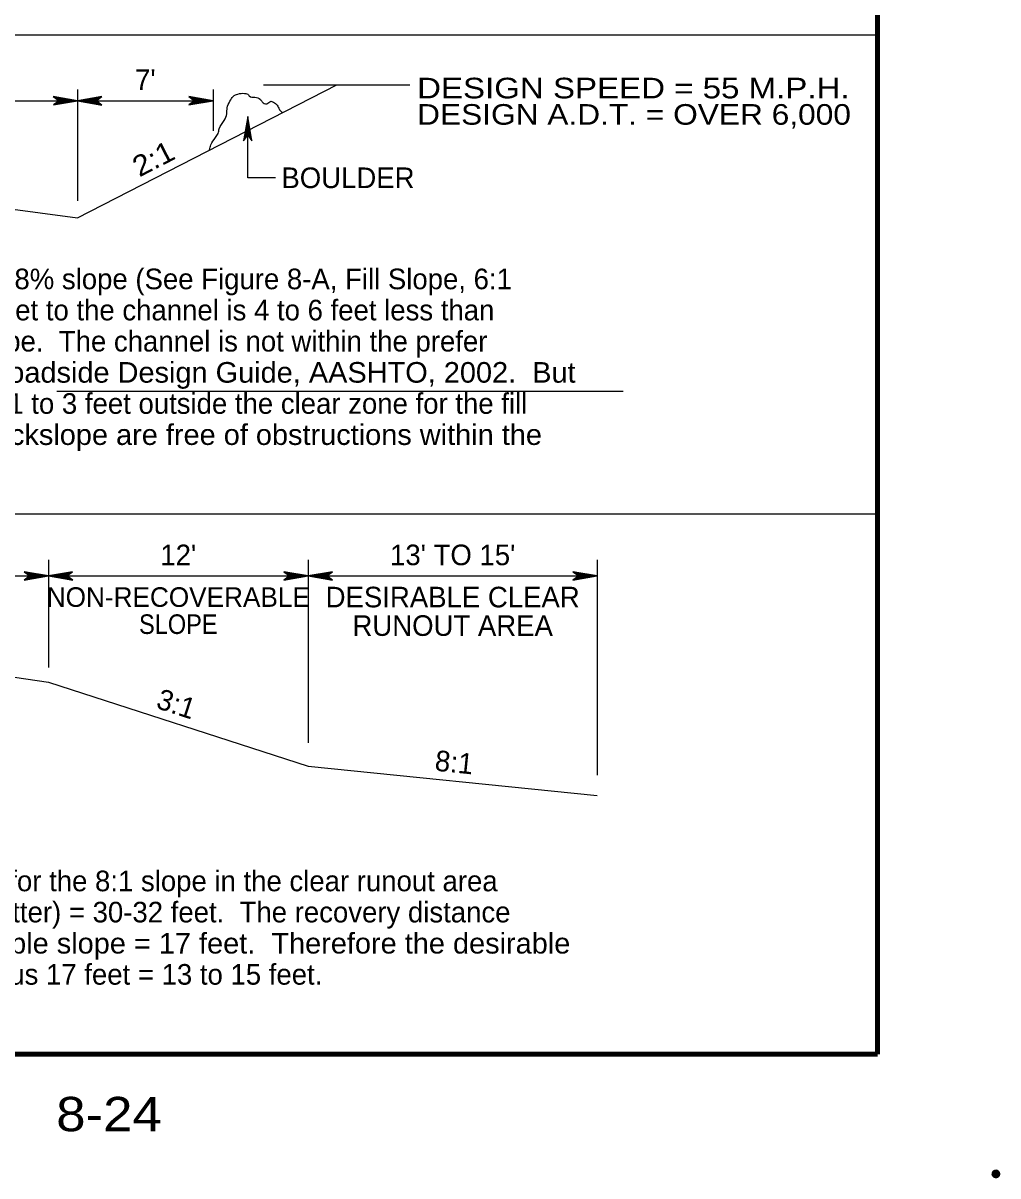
# Model space of a CAD drawing. Extents: x -15.691 to -15.016, y -14.8 to -13.916.
# Drawn here: x -15.3861 to -15.016, y -14.8 to -14.3626 of the extents above; entities that cross this region are included whole.
import ezdxf
from ezdxf.enums import TextEntityAlignment as Align

# ---------------------------------------------------------------- set-up
doc = ezdxf.new("R2010")
doc.units = 0
doc.header["$LTSCALE"] = 0.0031
doc.header["$PDMODE"] = 32
doc.header["$PDSIZE"] = 0.00155
for name, color, linetype, lineweight in [('1', 7, 'Continuous', 90), ('24', 7, 'Continuous', 25), ('5', 7, 'Continuous', 25)]:
    doc.layers.add(name, color=color, linetype=linetype, lineweight=lineweight)

msp = doc.modelspace()

# ---------------------------------------------------------------- linework, layer by layer
at = {"layer": '1'}
for p, q in [((-15.061808, -13.962108), (-15.061808, -14.753775)), ((-15.061808, -13.962108), (-15.061808, -14.753775)), ((-15.061808, -14.753775), (-15.645142, -14.753775))]:
    msp.add_line(p, q, dxfattribs=at)
msp.add_point((-15.016808, -14.799192), dxfattribs=at)
at = {"layer": '24'}
for p, q in [((-15.365383, -14.387742), (-15.365383, -14.429967)), ((-15.313992, -14.387742), (-15.313992, -14.403408)), ((-15.376492, -14.5662), (-15.376492, -14.607058)), ((-15.277883, -14.5662), (-15.277883, -14.635667)), ((-15.168158, -14.5662), (-15.168158, -14.647925))]:
    msp.add_line(p, q, dxfattribs=at)
for points in [[(-15.365383, -14.392042), (-15.374625, -14.390408), (-15.372417, -14.392042), (-15.374575, -14.39365), (-15.365383, -14.392042), (-15.365992, -14.392058), (-15.374358, -14.390525), (-15.372242, -14.392058), (-15.3742, -14.393517), (-15.366325, -14.392083), (-15.366633, -14.392042), (-15.3738, -14.390767), (-15.372192, -14.392058), (-15.37385, -14.393308), (-15.366775, -14.392042), (-15.367083, -14.392083), (-15.37335, -14.39095), (-15.372125, -14.392042), (-15.373375, -14.393167), (-15.367975, -14.392083), (-15.368492, -14.392083), (-15.372883, -14.391183), (-15.372025, -14.392008), (-15.37295, -14.392933), (-15.368592, -14.392042), (-15.369083, -14.392008), (-15.372383, -14.391442), (-15.37175, -14.392083), (-15.372433, -14.392717), (-15.369533, -14.392042), (-15.37, -14.391992), (-15.371983, -14.391617), (-15.371658, -14.392058), (-15.372192, -14.39255), (-15.370242, -14.392033), (-15.371533, -14.391733), (-15.37135, -14.392083), (-15.371917, -14.392442), (-15.370567, -14.392083), (-15.371417, -14.391875), (-15.371058, -14.39215), (-15.371467, -14.392317), (-15.371058, -14.392058), (-15.371275, -14.392008)], [(-15.365383, -14.392042), (-15.356142, -14.393675), (-15.35835, -14.392042), (-15.356192, -14.390433), (-15.365383, -14.392042), (-15.364767, -14.392025), (-15.3564, -14.39355), (-15.358525, -14.392017), (-15.356558, -14.390558), (-15.364433, -14.391992), (-15.364125, -14.392042), (-15.356958, -14.393308), (-15.358567, -14.392017), (-15.356917, -14.390767), (-15.363992, -14.392042), (-15.363683, -14.391992), (-15.357417, -14.393125), (-15.358633, -14.392042), (-15.357392, -14.390908), (-15.362792, -14.391992), (-15.362267, -14.391992), (-15.357883, -14.392892), (-15.358733, -14.392067), (-15.357817, -14.391142), (-15.362175, -14.392042), (-15.361683, -14.392067), (-15.358383, -14.392633), (-15.359017, -14.391992), (-15.358325, -14.391358), (-15.361225, -14.392042), (-15.360758, -14.392083), (-15.358783, -14.392467), (-15.359108, -14.392017), (-15.358567, -14.391525), (-15.360517, -14.392042), (-15.359225, -14.392342), (-15.359417, -14.391992), (-15.35885, -14.391642), (-15.360192, -14.391992), (-15.35935, -14.3922), (-15.3597, -14.391925), (-15.359292, -14.391758), (-15.3597, -14.392017), (-15.359492, -14.392067)], [(-15.313992, -14.392042), (-15.323233, -14.390408), (-15.321025, -14.392042), (-15.323183, -14.39365), (-15.313992, -14.392042), (-15.314608, -14.392058), (-15.322975, -14.390525), (-15.32085, -14.392058), (-15.322808, -14.393517), (-15.314942, -14.392083), (-15.315242, -14.392042), (-15.322417, -14.390767), (-15.320808, -14.392058), (-15.322458, -14.393308), (-15.315383, -14.392042), (-15.315692, -14.392083), (-15.321958, -14.39095), (-15.320742, -14.392042), (-15.321983, -14.393167), (-15.316583, -14.392083), (-15.317108, -14.392083), (-15.321492, -14.391183), (-15.320642, -14.392008), (-15.321558, -14.392933), (-15.3172, -14.392042), (-15.317692, -14.392008), (-15.320992, -14.391442), (-15.320358, -14.392083), (-15.321042, -14.392717), (-15.31815, -14.392042), (-15.318608, -14.391992), (-15.320592, -14.391617), (-15.320267, -14.392058), (-15.320808, -14.39255), (-15.31885, -14.392033), (-15.320142, -14.391733), (-15.319958, -14.392083), (-15.320525, -14.392442), (-15.319175, -14.392083), (-15.320025, -14.391875), (-15.319675, -14.39215), (-15.320075, -14.392317), (-15.319675, -14.392058), (-15.319883, -14.392008)], [(-15.448717, -14.392042), (-15.365383, -14.392042), (-15.313992, -14.392042)], [(-15.300817, -14.398025), (-15.30245, -14.407267), (-15.300817, -14.405058), (-15.299208, -14.407217), (-15.300817, -14.398025), (-15.3008, -14.398642), (-15.302325, -14.407008), (-15.300792, -14.404883), (-15.299333, -14.406842), (-15.300767, -14.398967), (-15.300817, -14.399275), (-15.302092, -14.40645), (-15.3008, -14.404842), (-15.299542, -14.406492), (-15.300817, -14.399417), (-15.300767, -14.399725), (-15.3019, -14.405992), (-15.300817, -14.404775), (-15.299692, -14.406017), (-15.300767, -14.400617), (-15.300767, -14.401142), (-15.301667, -14.405525), (-15.300842, -14.404675), (-15.299925, -14.405592), (-15.300817, -14.401233), (-15.300842, -14.401725), (-15.301408, -14.405025), (-15.300767, -14.404392), (-15.300133, -14.405075), (-15.300817, -14.402183), (-15.300858, -14.402642), (-15.301242, -14.404625), (-15.300792, -14.4043), (-15.3003, -14.404842), (-15.300817, -14.402883), (-15.301125, -14.404175), (-15.300767, -14.403992), (-15.300417, -14.404558), (-15.300767, -14.403208), (-15.300983, -14.404058), (-15.3007, -14.4037), (-15.300533, -14.404108), (-15.300792, -14.403708), (-15.300842, -14.403917)], [(-15.29025, -14.421267), (-15.300817, -14.421267), (-15.300817, -14.398025)], [(-15.518158, -14.572342), (-15.433433, -14.572342), (-15.376492, -14.572342), (-15.277883, -14.572342), (-15.168158, -14.572342)], [(-15.376492, -14.572342), (-15.385733, -14.570708), (-15.383525, -14.572342), (-15.385683, -14.573942), (-15.376492, -14.572342), (-15.377108, -14.572358), (-15.385475, -14.570825), (-15.38335, -14.572358), (-15.385308, -14.573817), (-15.377433, -14.572383), (-15.377742, -14.572342), (-15.384917, -14.571067), (-15.383308, -14.572358), (-15.384958, -14.573608), (-15.377883, -14.572333), (-15.378192, -14.572383), (-15.384458, -14.57125), (-15.383242, -14.572333), (-15.384483, -14.573467), (-15.379083, -14.572383), (-15.379608, -14.572383), (-15.383992, -14.571483), (-15.383142, -14.572308), (-15.384058, -14.573233), (-15.3797, -14.572342), (-15.380192, -14.572308), (-15.383492, -14.571742), (-15.382858, -14.572383), (-15.383542, -14.573017), (-15.38065, -14.572342), (-15.381108, -14.572292), (-15.383092, -14.571908), (-15.382767, -14.572358), (-15.383308, -14.57285), (-15.38135, -14.572333), (-15.382642, -14.572033), (-15.382458, -14.572383), (-15.383025, -14.572742), (-15.381675, -14.572383), (-15.382525, -14.572175), (-15.382167, -14.57245), (-15.382575, -14.572617), (-15.382175, -14.572358), (-15.382383, -14.572308)], [(-15.376492, -14.572342), (-15.36725, -14.573975), (-15.369458, -14.572342), (-15.3673, -14.570733), (-15.376492, -14.572342), (-15.375875, -14.572317), (-15.367508, -14.57385), (-15.369633, -14.572317), (-15.367675, -14.570858), (-15.37555, -14.572292), (-15.375242, -14.572342), (-15.368075, -14.573608), (-15.369683, -14.572317), (-15.368025, -14.571067), (-15.3751, -14.572342), (-15.374792, -14.572292), (-15.368525, -14.573425), (-15.369742, -14.572342), (-15.3685, -14.571208), (-15.3739, -14.572292), (-15.373375, -14.572292), (-15.368992, -14.573192), (-15.369842, -14.572367), (-15.368925, -14.571442), (-15.373283, -14.572342), (-15.372792, -14.572367), (-15.369492, -14.572933), (-15.370125, -14.572292), (-15.369442, -14.571658), (-15.372342, -14.572342), (-15.371875, -14.572383), (-15.369892, -14.572767), (-15.370217, -14.572317), (-15.369675, -14.571825), (-15.371633, -14.572342), (-15.370342, -14.572642), (-15.370525, -14.572292), (-15.369958, -14.571942), (-15.371308, -14.572292), (-15.370458, -14.5725), (-15.370817, -14.572225), (-15.370408, -14.572058), (-15.370808, -14.572317), (-15.3706, -14.572367)], [(-15.277883, -14.572342), (-15.287125, -14.570708), (-15.284917, -14.572342), (-15.287075, -14.573942), (-15.277883, -14.572342), (-15.278492, -14.572358), (-15.286867, -14.570825), (-15.284742, -14.572358), (-15.2867, -14.573817), (-15.278825, -14.572383), (-15.279133, -14.572342), (-15.2863, -14.571067), (-15.284692, -14.572358), (-15.28635, -14.573608), (-15.279275, -14.572333), (-15.279583, -14.572383), (-15.28585, -14.57125), (-15.284625, -14.572333), (-15.285875, -14.573467), (-15.280475, -14.572383), (-15.280992, -14.572383), (-15.285383, -14.571483), (-15.284533, -14.572308), (-15.28545, -14.573233), (-15.281092, -14.572342), (-15.281583, -14.572308), (-15.284883, -14.571742), (-15.28425, -14.572383), (-15.284933, -14.573017), (-15.282033, -14.572342), (-15.2825, -14.572292), (-15.284483, -14.571908), (-15.284158, -14.572358), (-15.284692, -14.57285), (-15.282742, -14.572333), (-15.284033, -14.572033), (-15.28385, -14.572383), (-15.284417, -14.572742), (-15.283067, -14.572383), (-15.283917, -14.572175), (-15.283558, -14.57245), (-15.283967, -14.572617), (-15.283558, -14.572358), (-15.283775, -14.572308)], [(-15.277883, -14.572342), (-15.268642, -14.573975), (-15.27085, -14.572342), (-15.268692, -14.570733), (-15.277883, -14.572342), (-15.277267, -14.572317), (-15.2689, -14.57385), (-15.271025, -14.572317), (-15.269067, -14.570858), (-15.276933, -14.572292), (-15.276625, -14.572342), (-15.269458, -14.573608), (-15.271067, -14.572317), (-15.269417, -14.571067), (-15.276492, -14.572342), (-15.276183, -14.572292), (-15.269917, -14.573425), (-15.271133, -14.572342), (-15.269892, -14.571208), (-15.275292, -14.572292), (-15.274767, -14.572292), (-15.270383, -14.573192), (-15.271233, -14.572367), (-15.270317, -14.571442), (-15.274675, -14.572342), (-15.274183, -14.572367), (-15.270883, -14.572933), (-15.271517, -14.572292), (-15.270833, -14.571658), (-15.273725, -14.572342), (-15.273258, -14.572383), (-15.271283, -14.572767), (-15.271608, -14.572317), (-15.271067, -14.571825), (-15.273025, -14.572342), (-15.271733, -14.572642), (-15.271917, -14.572292), (-15.27135, -14.571942), (-15.2727, -14.572292), (-15.27185, -14.5725), (-15.2722, -14.572225), (-15.2718, -14.572058), (-15.2722, -14.572317), (-15.271992, -14.572367)], [(-15.168158, -14.572342), (-15.1774, -14.570708), (-15.175192, -14.572342), (-15.17735, -14.573942), (-15.168158, -14.572342), (-15.168775, -14.572358), (-15.177142, -14.570825), (-15.175017, -14.572358), (-15.176975, -14.573817), (-15.169108, -14.572383), (-15.169408, -14.572342), (-15.176583, -14.571067), (-15.174975, -14.572358), (-15.176625, -14.573608), (-15.16955, -14.572333), (-15.169858, -14.572383), (-15.176125, -14.57125), (-15.174908, -14.572333), (-15.17615, -14.573467), (-15.17075, -14.572383), (-15.171275, -14.572383), (-15.175658, -14.571483), (-15.174808, -14.572308), (-15.175725, -14.573233), (-15.171367, -14.572342), (-15.171858, -14.572308), (-15.175158, -14.571742), (-15.174525, -14.572383), (-15.175208, -14.573017), (-15.172317, -14.572342), (-15.172775, -14.572292), (-15.174758, -14.571908), (-15.174433, -14.572358), (-15.174975, -14.57285), (-15.173017, -14.572333), (-15.174308, -14.572033), (-15.174125, -14.572383), (-15.174692, -14.572742), (-15.173342, -14.572383), (-15.174192, -14.572175), (-15.173842, -14.57245), (-15.174242, -14.572617), (-15.173842, -14.572358), (-15.17405, -14.572308)]]:
    msp.add_lwpolyline(points, dxfattribs=at)
at = {"layer": '5'}
for p, q in [((-15.645142, -14.367008), (-15.061808, -14.367008)), ((-15.294825, -14.385983), (-15.267042, -14.385983)), ((-15.373233, -14.5022), (-15.15825, -14.5022)), ((-15.645142, -14.5487), (-15.061808, -14.5487))]:
    msp.add_line(p, q, dxfattribs=at)
for points in [[(-15.518158, -14.419817), (-15.448717, -14.425375), (-15.365383, -14.436483), (-15.267042, -14.385983), (-15.239267, -14.385983)], [(-15.518158, -14.600117), (-15.433433, -14.604283), (-15.376492, -14.612617), (-15.277883, -14.644558), (-15.168158, -14.655675)]]:
    msp.add_lwpolyline(points, dxfattribs=at)
msp.add_spline([(-15.315383, -14.410692), (-15.314817, -14.408733), (-15.3131, -14.406042), (-15.312042, -14.404408), (-15.311633, -14.4027), (-15.309758, -14.399517), (-15.308783, -14.396992), (-15.308617, -14.394708), (-15.307558, -14.392183), (-15.306333, -14.390383), (-15.304542, -14.389492), (-15.302008, -14.389242), (-15.300542, -14.389817), (-15.300217, -14.390225), (-15.298183, -14.390717), (-15.295975, -14.391608), (-15.295325, -14.392425), (-15.293617, -14.393158), (-15.292067, -14.392258), (-15.290675, -14.392833), (-15.289375, -14.394142), (-15.288717, -14.395442), (-15.287742, -14.396425)], degree=3, dxfattribs=at)

# ---------------------------------------------------------------- texts
at = {"layer": '1'}
for s, height, p in [("7'", 0.007817, (-15.339683, -14.38795)), ('BOULDER', 0.007817, (-15.262775, -14.425175)), ("12'", 0.007817, (-15.327188, -14.56825)), ("13' TO 15'", 0.007817, (-15.223013, -14.56825)), ('NON-RECOVERABLE', 0.007426, (-15.327175, -14.584058)), ('DESIRABLE CLEAR', 0.007817, (-15.223017, -14.58425)), ('RUNOUT AREA', 0.007817, (-15.223017, -14.595067))]:
    msp.add_text(s, height=height, dxfattribs=at).set_placement(p, align=Align.CENTER)
for s, width, p in [('DESIGN SPEED = 55 M.P.H.', 1.2, (-15.236525, -14.391133)), ('DESIGN A.D.T. = OVER 6,000', 1.15, (-15.236525, -14.401133)), ('cross section area of Figure 3.6 of the Roadside Design Guide, AASHTO, 2002.  But', 1.05, (-15.586942, -14.499)), ('slope.  Since the channel bottom and backslope are free of obstructions within the', 1.05, (-15.586942, -14.522625)), ('before breakpoint of non-recoverable slope = 17 feet.  Therefore the desirable', 1.05, (-15.556358, -14.715592))]:
    msp.add_text(s, height=0.007817, dxfattribs=dict(at, width=width)).set_placement(p)
at = {"layer": '1', "width": 1.1}
msp.add_text('2:1', height=0.007817, rotation=27.181, dxfattribs=at).set_placement((-15.33486, -14.417509), align=Align.CENTER)
at = {"layer": '1'}
for s, p in [('The suggested clear zone distance for the 8% slope (See Figure 8-A, Fill Slope, 6:1', (-15.586942, -14.46355)), ('or flatter) = 22-24 feet.  The available 18 feet to the channel is 4 to 6 feet less than', (-15.586942, -14.475367)), ('the suggested recovery area for the fill slope.  The channel is not within the prefer', (-15.586942, -14.487183)), ('the Boulder has 25 feet available which is 1 to 3 feet outside the clear zone for the fill', (-15.586942, -14.510808)), ('The suggested clear zone distance for the 8:1 slope in the clear runout area', (-15.556358, -14.691958)), ('(See Figure 8-A, Fill Slope 6:1 or flatter) = 30-32 feet.  The recovery distance', (-15.556358, -14.703775)), ('clear runout area is : 30-32 feet minus 17 feet = 13 to 15 feet.', (-15.556358, -14.7274))]:
    msp.add_text(s, height=0.007817, dxfattribs=at).set_placement(p)
for s, height, width, p in [('SLOPE', 0.007426, 0.9, (-15.327179, -14.594333)), ('8-24', 0.01303, 1.15, (-15.353479, -14.783))]:
    msp.add_text(s, height=height, dxfattribs=dict(at, width=width)).set_placement(p, align=Align.CENTER)
for s, rotation, p in [('3:1', 342.051, (-15.329109, -14.624573)), ('8:1', 354.218, (-15.222815, -14.646896))]:
    msp.add_text(s, height=0.007817, rotation=rotation, dxfattribs=at).set_placement(p, align=Align.CENTER)

doc.saveas('drawing.dxf')
